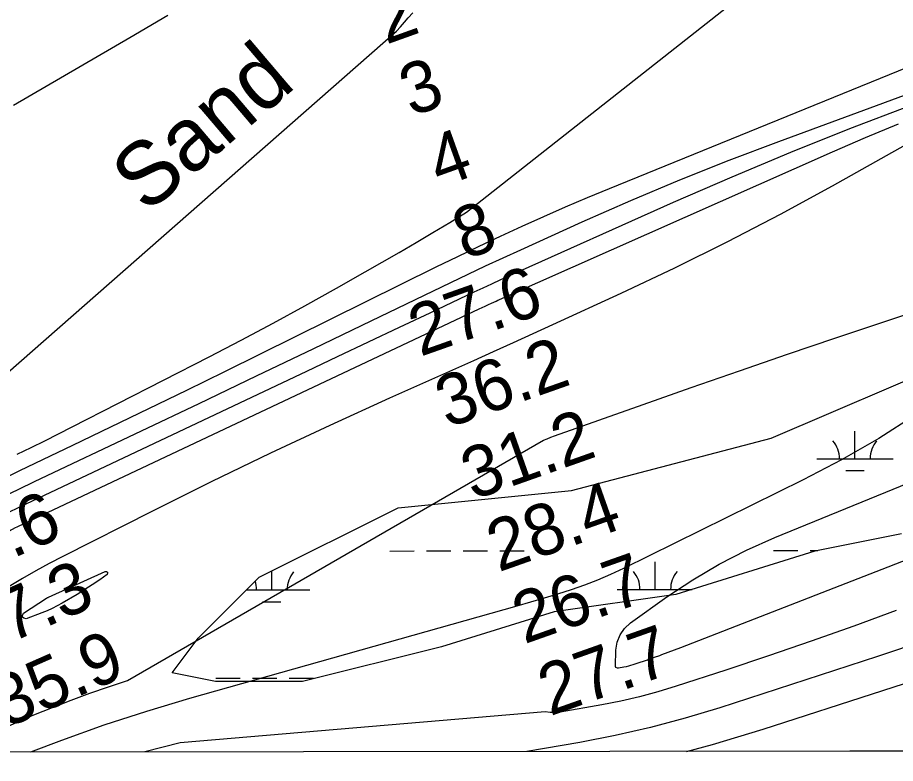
# Model space of a CAD drawing. Extents: x 3297753 to 3335611, y 652252 to 677623.
# Drawn here: x 3316441 to 3317590, y 657631 to 658606 of the extents above; entities that cross this region are included whole.
import ezdxf

# ---------------------------------------------------------------- set-up
doc = ezdxf.new("R2010")
doc.units = 0
for name, color, linetype in [('V-GRID-FRAM', 7, 'Continuous'), ('V-RIVR-EDGE', 7, 'Continuous'), ('V-RIVR-IDEN', 7, 'Continuous'), ('V-RIVR-RANG', 7, 'Continuous'), ('V-TOPO-DPTH', 7, 'Continuous'), ('V-TOPO-MAJR', 7, 'Continuous'), ('V-TOPO-MINR', 7, 'Continuous'), ('V-TOPO-WATR', 7, 'Continuous'), ('V-WETL-SWMP', 7, 'Continuous')]:
    doc.layers.add(name, color=color, linetype=linetype)

msp = doc.modelspace()

# ---------------------------------------------------------------- linework, layer by layer
at = {"layer": 'V-GRID-FRAM'}
msp.add_lwpolyline([(3301859.6, 675814.9), (3333399.1, 675847), (3333425.5, 657662.7), (3301870.2, 657630.6), (3301859.6, 675814.9)], dxfattribs=at)
at = {"layer": 'V-RIVR-EDGE'}
msp.add_spline([(3319472.9, 662096.8), (3319451.4, 662084.8), (3319431.4, 662073.3), (3319412.8, 662065.4), (3319386.6, 662059.7), (3319355.1, 662056.1), (3319321.5, 662047.4), (3319286.7, 662035.9), (3319261.8, 662024.4), (3319253.9, 662022.3), (3319244, 662022.3), (3319236.9, 662020.3), (3319220.3, 662007.1), (3319214.1, 661999.2), (3319197.9, 661992.6), (3319174.7, 661985.2), (3319135.2, 661974.5), (3319095.8, 661962.6), (3319061.8, 661950.7), (3319035.7, 661940.8), (3319017, 661932.5), (3319004.2, 661925.1), (3318977.6, 661914.4), (3318949.4, 661908.7), (3318929.1, 661903.3), (3318893.4, 661894.3), (3318836.2, 661878.7), (3318802.2, 661869.7), (3318784.3, 661864.3), (3318761.1, 661859.4), (3318735.4, 661848.3), (3318707.2, 661836.3), (3318683.9, 661831.8), (3318667.8, 661829.8), (3318647.9, 661824.9), (3318612.2, 661812.5), (3318583.6, 661801.4), (3318550.8, 661789.5), (3318517.2, 661780.8), (3318486.9, 661770.5), (3318459.1, 661757.8), (3318437.1, 661748.7), (3318401.1, 661732.6), (3318376.3, 661719.7), (3318350.3, 661712.4), (3318322.7, 661702.9), (3318295.6, 661690.6), (3318275.9, 661686.7), (3318257.8, 661681.1), (3318243.7, 661673.2), (3318214.4, 661661.5), (3318180.6, 661645.8), (3318148.4, 661630.1), (3318131.5, 661619.4), (3318111.1, 661604.8), (3318079.5, 661575), (3318056.4, 661560.4), (3318032.7, 661542.4), (3318016.3, 661532.3), (3317961.5, 661489.7), (3317862.7, 661415.5), (3317830, 661391.9), (3317829.4, 661388.6), (3317827.2, 661382.9), (3317810.8, 661375.6), (3317786, 661359.9), (3317761.1, 661342.5), (3317743.6, 661322.8), (3317726.1, 661300.9), (3317708.6, 661279), (3317696.7, 661270.6), (3317673.6, 661255.4), (3317601.3, 661201.5), (3317560.7, 661171.7), (3317529.1, 661153.2), (3317513.8, 661140.3), (3317483.9, 661117.2), (3317464.2, 661105.5), (3317423.5, 661083), (3317409.4, 661079.1), (3317401.5, 661079.1), (3317375, 661065.7), (3317364.3, 661058.9), (3317348.5, 661051.1), (3317330.5, 661046.6), (3317307.3, 661033.2), (3317289.3, 661024.8), (3317263.9, 661012.4), (3317240.8, 661008.5), (3317230.1, 661004), (3317228.4, 661000.1), (3317221.6, 660998.4), (3317196.2, 660991.2), (3317170.3, 660981.7), (3317149.4, 660978.3), (3317103.2, 660961), (3317073.3, 660949.8), (3317034.3, 660929.6), (3316996, 660910), (3316948, 660887), (3316914.7, 660873.5), (3316886, 660860.6), (3316880.9, 660856.2), (3316871.3, 660848.3), (3316865.7, 660846.6), (3316855.5, 660846.6), (3316850.4, 660846.6), (3316844.2, 660840.5), (3316839.7, 660839.9), (3316835.8, 660840.5), (3316830.7, 660836.6), (3316818.8, 660828.7), (3316813.8, 660828.1), (3316808.1, 660827), (3316803.6, 660827), (3316796.8, 660818.6), (3316785, 660809.6), (3316774.8, 660802.9), (3316771.4, 660796.1), (3316765.2, 660779.2), (3316755.6, 660759.5), (3316745.9, 660744.3), (3316732.4, 660728.6), (3316712.6, 660717.9), (3316683.9, 660703.4), (3316676.5, 660701.1), (3316664.7, 660695.5), (3316651.7, 660680.3), (3316633, 660666.9), (3316616.1, 660656.2), (3316590.1, 660637.1), (3316544.4, 660603.4), (3316510, 660581), (3316472.7, 660551.7), (3316428.7, 660523.1), (3316390.3, 660495.6), (3316363.8, 660477.6), (3316349.7, 660469.8), (3316341.2, 660464.7), (3316335, 660464.7), (3316325.4, 660464.8), (3316313.6, 660461.4), (3316289.9, 660457), (3316257.2, 660443.5), (3316237.5, 660436.3), (3316207, 660423.9), (3316177.1, 660405.4), (3316154.5, 660393.1), (3316131.9, 660375.1), (3316110.5, 660362.2), (3316095.3, 660353.2), (3316080, 660338), (3316051.2, 660312.7), (3316013.9, 660270.6), (3315988.5, 660245.8), (3315960.3, 660217.2), (3315939.9, 660200.9), (3315925.8, 660185.1), (3315911.1, 660173.9), (3315895.3, 660159.9), (3315882.9, 660145.8), (3315867.6, 660130.1), (3315849, 660120), (3315837.7, 660109.3), (3315808.9, 660080.1), (3315786.9, 660062.1), (3315758.1, 660038.5), (3315733.8, 660018.8), (3315725.3, 660002.5), (3315692, 659976.7), (3315659.8, 659949.1), (3315603.4, 659904.2), (3315571.2, 659873.3), (3315569.5, 659873.3), (3315558.8, 659868.8), (3315547.5, 659863.2), (3315527.7, 659844.1), (3315506.3, 659828.4), (3315477.5, 659812.1), (3315461.1, 659805.9), (3315440.8, 659793.6), (3315429.5, 659781.8), (3315402.4, 659758.2), (3315361.8, 659731.8), (3315304.2, 659696.4), (3315255.7, 659666.7), (3315169.9, 659624.7), (3315140, 659611.8), (3315123.7, 659603.4), (3315098.8, 659588.8), (3315044.6, 659551.1), (3314989.9, 659507.3), (3314954.3, 659474.7), (3314934, 659462.4), (3314926.1, 659452.8), (3314915.9, 659440.5), (3314897.8, 659423.6), (3314866.8, 659396.1), (3314844.7, 659376.4), (3314848.7, 659370.7), (3314825, 659355), (3314801.8, 659342.7), (3314762.3, 659320.8), (3314730.2, 659303.4), (3314711, 659290.5), (3314664.7, 659256.3), (3314628.6, 659235.5), (3314603.2, 659218.1), (3314584.5, 659209.7), (3314564.8, 659208), (3314555.8, 659204.7), (3314546.8, 659196.2), (3314528.1, 659174.9), (3314492.5, 659118.6), (3314473.8, 659095), (3314450.7, 659074.8), (3314428.7, 659060.2), (3314423, 659054.6), (3314416.2, 659044.4), (3314398.1, 659027.6), (3314375.6, 659007.9), (3314366.5, 659005.1), (3314353.6, 659002.3), (3314347.4, 658997.3), (3314346.8, 658988.8), (3314351.3, 658983.2), (3314350.7, 658974.2), (3314342.8, 658961.8), (3314329.2, 658955.1), (3314311.7, 658940.4), (3314310, 658930.3), (3314294.2, 658921.9), (3314283.5, 658914.6), (3314276.1, 658903.9), (3314272.7, 658896), (3314237.7, 658871.3), (3314206.7, 658853.4), (3314198.2, 658851.1), (3314192, 658850.6), (3314180.2, 658846.1), (3314172.3, 658836.5), (3314164.4, 658823.6), (3314142.3, 658810.1), (3314120.9, 658792.7), (3314097.2, 658778.7), (3314086.5, 658769.1), (3314082.5, 658762.9), (3314080.2, 658754.5), (3314072.3, 658750), (3314036.8, 658734.3), (3314006.3, 658722), (3313997.3, 658716.4), (3313939.7, 658673.7), (3313888.3, 658635), (3313863.5, 658615.3), (3313820.6, 658586.7), (3313772.6, 658558), (3313732, 658532.8), (3313718.5, 658524.4), (3313711.1, 658521.6), (3313702.7, 658521.6), (3313693.1, 658518.8), (3313674.5, 658511.5), (3313646.8, 658494.7), (3313626.5, 658479), (3313619.7, 658475), (3313610.1, 658464.3), (3313605, 658449.1), (3313597.1, 658444.7), (3313577.9, 658428.9), (3313554.8, 658407.6), (3313537.8, 658387.3), (3313525.4, 658364.2), (3313506.1, 658331.6), (3313489.7, 658309.7)], degree=3, dxfattribs=at)
at = {"layer": 'V-TOPO-DPTH'}
for points in [[(3316391.7, 658110.5), (3316936.7, 658588.7), (3316941.8, 658594.5), (3316947, 658600.4), (3316952.2, 658606.2), (3316958.2, 658612.9)], [(3316391.7, 658110.5), (3316936.7, 658588.7), (3316941.8, 658594.5), (3316947, 658600.4), (3316952.2, 658606.2), (3316958.2, 658612.9)], [(3317703.6, 658581.2), (3317215, 658382.4), (3317186.3, 658370.5), (3317157.7, 658358.4), (3317129.2, 658345.9), (3317100.8, 658333.1), (3317072.6, 658320.1), (3317044.4, 658306.9), (3317016.4, 658293.4), (3316988.4, 658279.8), (3316711.5, 658143.1), (3316661.9, 658118.7), (3316612.2, 658094.5), (3316562.4, 658070.5), (3316512.6, 658046.6), (3316473.5, 658027.9), (3316443.2, 658013.4), (3316412.9, 657998.8)], [(3317957.2, 657647.4), (3317316.5, 657646.3), (3317350.4, 657655.5), (3317416.7, 657675.4), (3317886.5, 657827.2)]]:
    msp.add_lwpolyline(points, dxfattribs=at)
at = {"layer": 'V-TOPO-MAJR'}
for points in [[(3316012.9, 657645), (3316424.8, 657931.4), (3316427, 657933), (3316429.4, 657934.5), (3316431.7, 657935.8), (3316434.2, 657937.2), (3316438, 657939.2), (3316440.1, 657940.3), (3316441.2, 657940.8), (3317044.8, 658225.2), (3317048.9, 658227.1), (3317053, 658229), (3317057.1, 658230.9), (3317061.2, 658232.8), (3317067.2, 658235.6), (3317069.4, 658236.6), (3317070.5, 658237.1), (3317071.7, 658237.6), (3317507.5, 658431), (3317550.5, 658449.5), (3317593.6, 658467.6)], [(3317615.6, 658086.2), (3317568.2, 658055.8), (3317519.2, 658027.9), (3317469.2, 658001.6), (3317233.7, 657885.5), (3317216.9, 657877.7), (3317200, 657870.4), (3317182.7, 657863.8), (3317165.2, 657857.7), (3317147.5, 657852.1), (3317129.8, 657846.7), (3317112.1, 657841.4), (3317094.3, 657836.3), (3316665.9, 657715.4), (3316609.5, 657698.6), (3316553.5, 657680.6), (3316498.1, 657660.8), (3316457.6, 657645.5)], [(3317853.5, 657993.9), (3317316.4, 657785.1), (3317308.3, 657781.9), (3317300.1, 657778.8), (3317292, 657775.7), (3317283.8, 657772.6), (3317280.9, 657771.6), (3317274.2, 657769.1), (3317267.5, 657766.7), (3317260.7, 657764.3), (3317253.9, 657762.1), (3317246, 657759.5), (3317243.1, 657758.6), (3317240.2, 657757.8), (3317237.2, 657757.2), (3317234.2, 657756.6), (3317227.5, 657755.4), (3317226, 657755.3), (3317224, 657756), (3317223.6, 657756.5), (3317223.3, 657757.1), (3317223.2, 657757.7), (3317223.9, 657778.8), (3317225.7, 657789.3), (3317229.3, 657798.9), (3317235.3, 657807.2), (3317243, 657814.6), (3317290.7, 657848.5), (3317324.4, 657870.7), (3317359, 657891.4), (3317394.9, 657909.6), (3317431.8, 657926.1), (3317834.5, 658090.6)]]:
    msp.add_lwpolyline(points, dxfattribs=at)
at = {"layer": 'V-TOPO-MINR'}
for points in [[(3316440.4, 658035.3), (3316458.4, 658044), (3316476.3, 658052.8), (3316494.2, 658061.7), (3316512, 658070.8), (3316691.6, 658162.8), (3316733.5, 658184.6), (3316775.3, 658206.7), (3316816.8, 658229.4), (3316858.1, 658252.4), (3316895.9, 658273.8), (3316918.1, 658286.5), (3316940.3, 658299.3), (3316962.4, 658312.2), (3316984.4, 658325.3), (3317006.4, 658338.5), (3317028.3, 658351.8), (3317485.7, 658712.2)], [(3316435.6, 658492), (3316587.6, 658580.4), (3316637.3, 658609.6)], [(3317703.6, 658581.2), (3317215, 658382.4), (3317186.3, 658370.5), (3317157.7, 658358.4), (3317129.2, 658345.9), (3317100.8, 658333.1), (3317072.6, 658320.1), (3317044.4, 658306.9), (3317016.4, 658293.4), (3316988.4, 658279.8), (3316711.5, 658143.1), (3316661.9, 658118.7), (3316612.2, 658094.5), (3316562.4, 658070.5), (3316512.6, 658046.6), (3316473.5, 658027.9), (3316443.2, 658013.4), (3316412.9, 657998.8)], [(3316421.5, 657979.3), (3316442.2, 657989.4), (3316462.9, 657999.3), (3316603.1, 658065.9), (3316678.3, 658101.7), (3316753.3, 658137.6), (3316828.4, 658173.6), (3316903.4, 658209.7), (3317007.7, 658260), (3317030.5, 658270.9), (3317053.4, 658281.7), (3317076.3, 658292.3), (3317099.4, 658302.8), (3317179.9, 658339.3), (3317243.5, 658367.2), (3317307.5, 658394.3), (3317372, 658419.9), (3317437, 658444.5), (3317712.9, 658545.8)], [(3316430.3, 657959.6), (3316441.2, 657965), (3316452.2, 657970.2), (3316819.3, 658144), (3316859.7, 658163.1), (3316900.1, 658182.2), (3316940.5, 658201.3), (3316980.9, 658220.3), (3317038.5, 658247.5), (3317050.1, 658252.9), (3317061.7, 658258.3), (3317073.3, 658263.6), (3317085, 658268.9), (3317299.5, 658365), (3317375.9, 658398.3), (3317452.7, 658430.6), (3317530.2, 658461.3), (3317608.1, 658490.9)], [(3317602.5, 658439.5), (3317506.8, 658386), (3317438.7, 658348.9), (3317370, 658312.9), (3317300.5, 658278.6), (3317230.4, 658245.4), (3317141.1, 658204.5), (3317115.2, 658192.6), (3317089.3, 658180.9), (3317063.4, 658169.2), (3317037.4, 658157.5), (3316927.5, 658108.5), (3316849.4, 658072.9), (3316771.6, 658036.6), (3316694.3, 657999.1), (3316617.4, 657960.8), (3316500.2, 657901.4), (3316482.3, 657892), (3316464.5, 657882.4), (3316447, 657872.4), (3316429.6, 657862.1)], [(3316356.4, 657645.4), (3316374, 657653.7), (3316390.8, 657661.8), (3316414.4, 657672.9), (3316438.2, 657683.7), (3316462.2, 657694), (3316486.3, 657704), (3316510.7, 657713.4), (3316535.2, 657722.5), (3316559.8, 657731), (3316584.7, 657739.1), (3317129.3, 658053.4), (3317134.1, 658055.4), (3317138.8, 658057.3), (3317143.7, 658059.1), (3317259.6, 658100.3), (3317322.5, 658122.5), (3317385.5, 658144.4), (3317448.6, 658166), (3317511.8, 658187.3), (3317809.7, 658287)], [(3316538.5, 657864.3), (3316528.6, 657858), (3316518.6, 657851.8), (3316499.2, 657840.2), (3316492.7, 657836.6), (3316486.2, 657833.2), (3316479.5, 657830.2), (3316472.6, 657827.5), (3316452.2, 657819.9), (3316449, 657820.5), (3316447.1, 657821.8), (3316447.2, 657824.1), (3316448.5, 657827.1), (3316478.5, 657846.7), (3316479.9, 657847.5), (3316480.6, 657847.9), (3316481.3, 657848.2), (3316555.4, 657881.9), (3316557.3, 657881.6), (3316558.5, 657880.9), (3316558.5, 657879.5), (3316557.8, 657877.7), (3316548.2, 657870.9), (3316538.5, 657864.3)], [(3317590.8, 657830.7), (3317535.3, 657810.3), (3317479.6, 657790.4), (3317423.7, 657771.3), (3317367.6, 657752.6), (3317302.9, 657731.6), (3317278.9, 657724.3), (3317254.7, 657717.7), (3317230.2, 657712.2), (3317205.5, 657707.4), (3317150.8, 657697.9), (3317144.3, 657697.2), (3317137.7, 657697.1), (3317131.3, 657698), (3316653.7, 657657.4), (3316607.1, 657645.6)], [(3317316.5, 657646.3), (3317350.4, 657655.5), (3317416.7, 657675.4), (3317886.5, 657827.2)], [(3317630.1, 657791.8), (3317566.4, 657770.6), (3317359.8, 657703.5), (3317314.6, 657689.9), (3317269.1, 657677.6), (3317223.1, 657667.2), (3317176.8, 657658.2), (3317107.5, 657646.1)]]:
    msp.add_lwpolyline(points, dxfattribs=at)
at = {"layer": 'V-TOPO-WATR'}
msp.add_lwpolyline([(3316391.7, 658110.5), (3316936.7, 658588.7), (3316941.8, 658594.5), (3316947, 658600.4), (3316952.2, 658606.2), (3316958.2, 658612.9)], dxfattribs=at)
at = {"layer": 'V-WETL-SWMP'}
for p, q in [((3317536.7, 658029.2), (3317536.6, 658065.2)), ((3317486.7, 658029.2), (3317586.7, 658029.3)), ((3317524.7, 658013.8), (3317548.7, 658013.8)), ((3316928, 657908.5), (3316960, 657908.6)), ((3316976, 657908.6), (3317008, 657908.6)), ((3317024, 657908.6), (3317056, 657908.7)), ((3317072, 657908.7), (3317104, 657908.7)), ((3317430, 657909.1), (3317462, 657909.1)), ((3317478, 657909.1), (3317488, 657909.1)), ((3317275.4, 657858.2), (3317275.4, 657894.2)), ((3316773.5, 657857.6), (3316773.5, 657882.6)), ((3316740.2, 657857.6), (3316823.5, 657857.7)), ((3317225.4, 657858.1), (3317323.7, 657858.2)), ((3316761.5, 657842.2), (3316785.5, 657842.2)), ((3316700.2, 657742.1), (3316732.2, 657742.2)), ((3316748.2, 657742.2), (3316780.2, 657742.2)), ((3316796.2, 657742.2), (3316828.2, 657742.3))]:
    msp.add_line(p, q, dxfattribs=at)
msp.add_lwpolyline([(3317597.8, 657931.1), (3317484.1, 657908.3), (3317302.3, 657851.5), (3317143.2, 657828.8), (3316995.5, 657783.3), (3316813.7, 657737.9), (3316700, 657737.9), (3316643.2, 657749.2), (3316677.3, 657794.7), (3316756.8, 657874.2), (3316938.7, 657965.2), (3317165.9, 657987.9), (3317427.3, 658056.1), (3317666, 658158.4)], dxfattribs=at)
for centre, start, end in [((3317481.4, 658029.6), 359.2865, 40.8301), ((3317591.9, 658029.8), 139.2865, 180.8301), ((3316828.8, 657858.2), 139.2865, 180.8301), ((3317220.2, 657858.6), 359.2865, 40.8301), ((3317330.7, 657858.7), 139.2865, 180.8301), ((3316718.3, 657858.1), 359.2865, 18.3159)]:
    msp.add_arc(centre, 35.2, start, end, dxfattribs=at)

# ---------------------------------------------------------------- texts
at = {"layer": 'V-RIVR-IDEN'}
msp.add_text('Sand', height=83, rotation=40.3642, dxfattribs=at).set_placement((3316609.5, 658348.7))
at = {"layer": 'V-RIVR-RANG'}
for s, rotation, p in [('2', 19.768, (3316923.1, 658570.9)), ('3', 19.768, (3316956.2, 658476.5)), ('4', 19.768, (3316993.1, 658383.5)), ('8', 19.768, (3317025.9, 658289.1)), ('27.6', 19.4883, (3316967.8, 658162.5)), ('36.2', 19.4883, (3317003.1, 658069)), ('31.2', 19.4883, (3317036.7, 657974.8)), ('28.4', 19.4883, (3317070.3, 657880.6)), ('27.6', 23.7383, (3316343.1, 657858.4)), ('26.7', 19.4883, (3317103.9, 657786.4)), ('37.3', 23.7383, (3316385.3, 657767.7)), ('27.7', 19.4883, (3317137.5, 657692.2)), ('35.9', 23.7383, (3316425.6, 657676.1))]:
    msp.add_text(s, height=67, rotation=rotation, dxfattribs=at).set_placement(p)

doc.saveas('drawing.dxf')
